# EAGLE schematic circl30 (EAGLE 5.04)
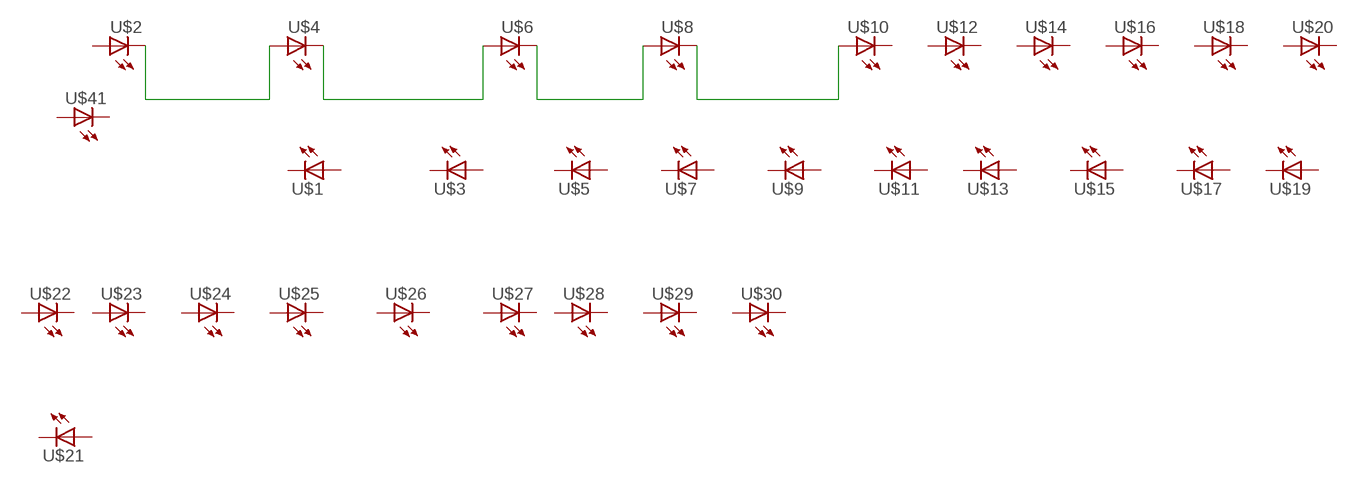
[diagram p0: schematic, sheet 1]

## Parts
U$1  LED5MM  [LED5MM]
U$2  LED5MM  [LED5MM]
U$3  LED5MM  [LED5MM]
U$4  LED5MM  [LED5MM]
U$5  LED5MM  [LED5MM]
U$6  LED5MM  [LED5MM]
U$7  LED5MM  [LED5MM]
U$8  LED5MM  [LED5MM]
U$9  LED5MM  [LED5MM]
U$10  LED5MM  [LED5MM]
U$11  LED5MM  [LED5MM]
U$12  LED5MM  [LED5MM]
U$13  LED5MM  [LED5MM]
U$14  LED5MM  [LED5MM]
U$15  LED5MM  [LED5MM]
U$16  LED5MM  [LED5MM]
U$17  LED5MM  [LED5MM]
U$18  LED5MM  [LED5MM]
U$19  LED5MM  [LED5MM]
U$20  LED5MM  [LED5MM]
U$21  LED5MM  [LED5MM]
U$22  LED5MM  [LED5MM]
U$23  LED5MM  [LED5MM]
U$24  LED5MM  [LED5MM]
U$25  LED5MM  [LED5MM]
U$26  LED5MM  [LED5MM]
U$27  LED5MM  [LED5MM]
U$28  LED5MM  [LED5MM]
U$29  LED5MM  [LED5MM]
U$30  LED5MM  [LED5MM]
U$41  LED5MM  [LED5MM]

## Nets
N$2: U$2.K(C) U$4.A
N$3: U$4.K(C) U$6.A
N$4: U$6.K(C) U$8.A
N$5: U$8.K(C) U$10.A
Unconnected: U$1.A U$1.K(C) U$2.A U$3.A U$3.K(C) U$5.A U$5.K(C) U$7.A U$7.K(C) U$9.A U$9.K(C) U$10.K(C) U$11.A U$11.K(C) U$12.A U$12.K(C) U$13.A U$13.K(C) U$14.A U$14.K(C) U$15.A U$15.K(C) U$16.A U$16.K(C) U$17.A U$17.K(C) U$18.A U$18.K(C) U$19.A U$19.K(C) U$20.A U$20.K(C) U$21.A U$21.K(C) U$22.A U$22.K(C) U$23.A U$23.K(C) U$24.A U$24.K(C) U$25.A U$25.K(C) U$26.A U$26.K(C) U$27.A U$27.K(C) U$28.A U$28.K(C) U$29.A U$29.K(C) U$30.A U$30.K(C) U$41.A U$41.K(C)

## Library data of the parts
U$1-U$30 U$41 = led(2):LED: LED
